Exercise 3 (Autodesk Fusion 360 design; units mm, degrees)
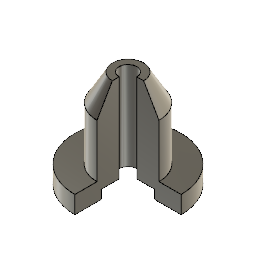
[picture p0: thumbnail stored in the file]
sketch "Sketch1" plane through (0, 0, 0) normal (0, 1, 0) x axis (1, 0, 0)
  line L1 (0, -58.5554) -> (0, 0)
  line L2 (55.097, 0) -> (0, 0)
  line L3 (15, -5) -> (15, 0)
  line L4 (5, -5) -> (15, -5)
  line L5 (5, -55) -> (5, -5)
  line L6 (8.8397, -55) -> (5, -55)
  line L7 (17.5, -40) -> (8.8397, -55)
  line L8 (17.5, -10) -> (17.5, -40)
  line L9 (30, -10) -> (17.5, -10)
  line L10 (30, 0) -> (30, -10)
  line L11 (30, 0) -> (15, 0)
  point P1 (0, 0)
  point P2 (0, 0)
  point P4 (0, 0)
  point P6 (15, 0)
  point P14 (30, 0)
  point P7 (15, -5)
  point P13 (30, -10)
  point P11 (17.5, -40)
  coincident P1 P2
  vertical L1
  coincident P1 P4
  perpendicular L1 L2
  coincident L2 P6
  perpendicular L2 L3
  perpendicular L3 L4
  perpendicular L4 L5
  perpendicular L5 L6
  perpendicular L6 L8
  perpendicular L5 L9
  coincident L2 P14
  perpendicular L2 L10
  dimension "d2" = 30
  dimension "d3" = 60
  dimension "d4" distance P6 P7 = 5
  dimension "d5" distance P13 P14 = 10
  dimension "d6" = 10
  dimension "d7" angle L7 L8 = 30
  dimension "d8" distance L6 P11 = 15
  dimension "d9" = 35
  dimension "d10" distance L2 L6 = 55
revolve "Revolve1" sketch "Sketch1" AlongAngle 270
